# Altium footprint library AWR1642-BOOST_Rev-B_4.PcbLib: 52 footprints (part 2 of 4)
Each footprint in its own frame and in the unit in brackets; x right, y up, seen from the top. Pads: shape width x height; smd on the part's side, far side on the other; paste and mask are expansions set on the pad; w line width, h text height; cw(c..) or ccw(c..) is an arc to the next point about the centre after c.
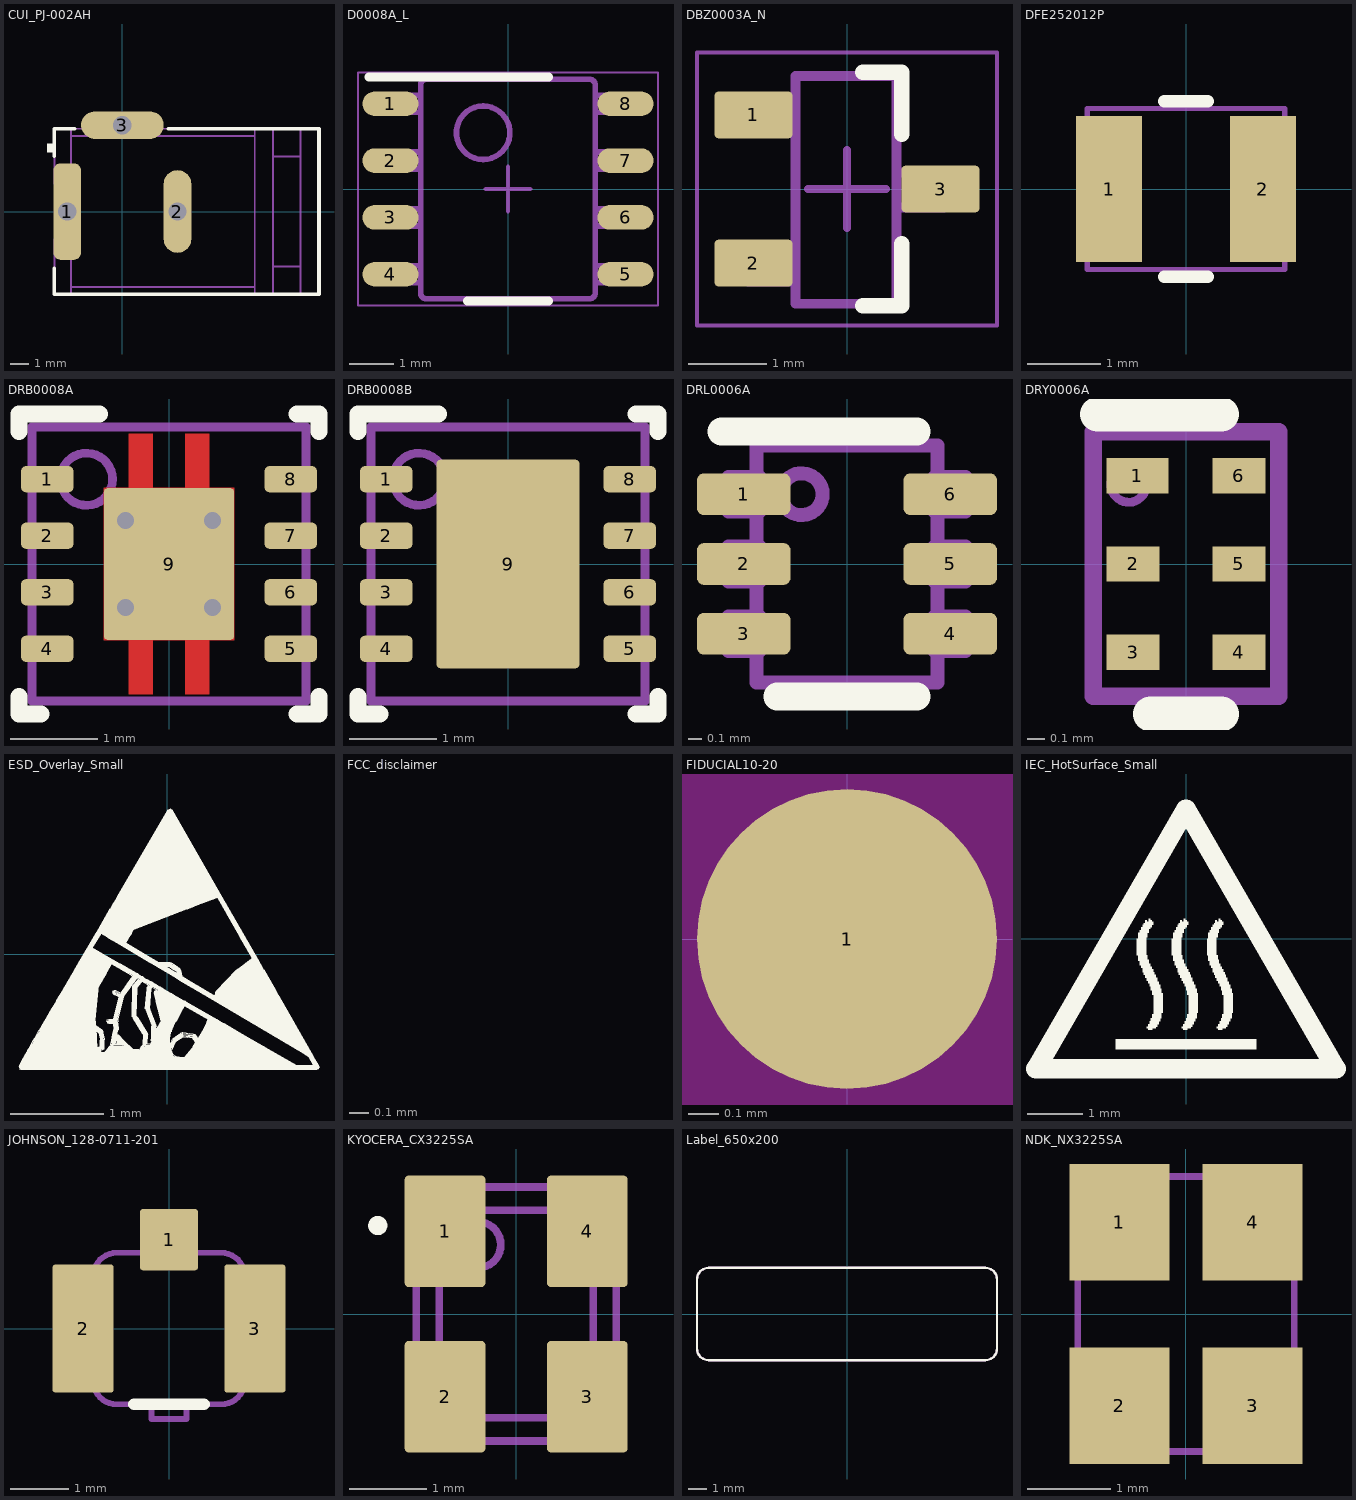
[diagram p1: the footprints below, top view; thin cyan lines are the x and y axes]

## CUI_PJ-002AH [mm] "DC POWER JACK, R/A, TH"
height 11.2
pads (3):
  rrect50% 1.5x5.25 hole 1 square: 1(-3,0)
  oval 1.5x4.5 hole 1 square: 2(3,0)
  oval 4.5x1.5 hole 1 square: 3(0,4.7)
Top Overlay:
  rectangle: -4.101,3.2 -3.701,3.7
  lines w0.2: -3.7,-3.1 -3.7,-4.5 -2.8,-4.5 7.2,-4.5 8.2,-4.5 9.7,-4.5 10.7,-4.5 10.7,4.5 9.7,4.5 8.2,4.5 7.2,4.5 2.5,4.5 ; -3.7,3 -3.7,4.5 -2.8,4.5 -2.6,4.5
Mechanical 5:
  lines w0.1: -1.25,4.5 -1.25,4.9 1.25,4.9 1.25,4.5 ; 7.2,-4.1 -2.8,-4.1 ; 7.2,4.1 -2.8,4.1 ; 8.2,-3 9.7,-3 ; 8.2,3 9.7,3 ; -3.18,-1.5 -3.18,1.5 ; -3.18,-1.5 -3.7,-1.5 -3.7,-4.5 -2.8,-4.5 ; -3.18,-1.5 -2.82,-1.5 -2.82,1.5 -3.18,1.5 ; -3.18,1.5 -3.7,1.5 -3.7,4.5 -2.8,4.5 ; -2.8,-4.5 -2.8,-4.1 ; -2.8,-4.5 7.2,-4.5 ; -2.8,-4.1 -2.8,4.1 ; -2.8,4.1 -2.8,4.5 ; -2.8,4.5 7.2,4.5 ; 7.2,-4.5 7.2,4.5 ; 7.2,-4.5 8.2,-4.5 ; 7.2,4.5 8.2,4.5 ; 8.2,-4.5 8.2,4.5 ; 8.2,-4.5 9.7,-4.5 ; 8.2,4.5 9.7,4.5 ; 9.7,-4.5 9.7,4.5 ; 9.7,-4.5 10.7,-4.5 10.7,4.5 9.7,4.5
  text ".Designator" at -4.632,-0.63 h1.02
3D body: height 11, standoff -3.5, extent -3.7,-4.5 10.7,4.9

## D0008A_L [mm] "SOIC, 8-Leads, Body 4.9x3.9mm, Pitch 1.27mm, IPC High Density"
height 1.75
pads (8):
  oval 1.25x0.55 smd: 1(-2.625,1.905) 2(-2.625,0.635) 3(-2.625,-0.635) 4(-2.625,-1.905) 5(2.625,-1.905) 6(2.625,-0.635) 7(2.625,0.635) 8(2.625,1.905)
Top Overlay:
  lines w0.2: -3.1,2.5 0.9,2.5 ; -0.9,-2.5 0.9,-2.5
Mechanical 5:
  lines w0.127: -2.375,-2.095 -1.995,-2.095 -1.952,-2.095 -1.952,-1.715 -1.995,-1.715 -2.375,-1.715 ; -2.375,-2.095 -2.589,-2.095 -3.002,-2.095 -3.002,-1.715 -2.589,-1.715 -2.375,-1.715 ; -2.375,-2.095 -2.375,-1.715 ; -2.375,-0.825 -1.995,-0.825 -1.952,-0.825 -1.952,-0.445 -1.995,-0.445 -2.375,-0.445 ; -2.375,-0.825 -2.589,-0.825 -3.002,-0.825 -3.002,-0.445 -2.589,-0.445 -2.375,-0.445 ; -2.375,-0.825 -2.375,-0.445 ; -2.375,0.445 -1.995,0.445 -1.952,0.445 -1.952,0.825 -1.995,0.825 -2.375,0.825 ; -2.375,0.445 -2.589,0.445 -3.002,0.445 -3.002,0.825 -2.589,0.825 -2.375,0.825 ; -2.375,0.445 -2.375,0.825 ; -2.375,1.715 -1.995,1.715 -1.952,1.715 -1.952,2.095 -1.995,2.095 -2.375,2.095 ; -2.375,1.715 -2.589,1.715 -3.002,1.715 -3.002,2.095 -2.589,2.095 -2.375,2.095 ; -2.375,1.715 -2.375,2.095 ; -0.332,-2.45 -1.825,-2.45 -1.826,-2.45 cw(c-1.825,-2.323) -1.952,-2.324 -1.952,-2.323 -1.952,2.323 -1.952,2.324 cw(c-1.825,2.323) -1.826,2.45 -1.825,2.45 -0.332,2.45 ; -0.332,-2.45 -0.182,-2.45 ; -0.332,-2.45 -0.182,-2.45 ; -0.332,2.45 -0.182,2.45 ; -0.332,2.45 -0.182,2.45 ; -0.182,-2.45 0.178,-2.45 ; -0.182,2.45 0.178,2.45 ; 0.178,-2.45 0.328,-2.45 ; 0.178,-2.45 0.328,-2.45 ; 0.178,2.45 0.328,2.45 ; 0.178,2.45 0.328,2.45 ; 0.328,-2.45 1.821,-2.45 1.822,-2.45 ccw(c1.821,-2.323) 1.948,-2.324 1.948,-2.323 1.948,2.323 1.948,2.324 ccw(c1.821,2.323) 1.822,2.45 1.821,2.45 0.328,2.45 ; 2.371,-2.095 2.585,-2.095 2.998,-2.095 2.998,-1.715 2.585,-1.715 2.371,-1.715 ; 2.371,-2.095 1.991,-2.095 1.948,-2.095 1.948,-1.715 1.991,-1.715 2.371,-1.715 ; 2.371,-2.095 2.371,-1.715 ; 2.371,-0.825 2.585,-0.825 2.998,-0.825 2.998,-0.445 2.585,-0.445 2.371,-0.445 ; 2.371,-0.825 1.991,-0.825 1.948,-0.825 1.948,-0.445 1.991,-0.445 2.371,-0.445 ; 2.371,-0.825 2.371,-0.445 ; 2.371,0.445 2.585,0.445 2.998,0.445 2.998,0.825 2.585,0.825 2.371,0.825 ; 2.371,0.445 1.991,0.445 1.948,0.445 1.948,0.825 1.991,0.825 2.371,0.825 ; 2.371,0.445 2.371,0.825 ; 2.371,1.715 2.585,1.715 2.998,1.715 2.998,2.095 2.585,2.095 2.371,2.095 ; 2.371,1.715 1.991,1.715 1.948,1.715 1.948,2.095 1.991,2.095 2.371,2.095 ; 2.371,1.715 2.371,2.095 ; -0.555,0.659 cw(c-0.555,1.256) -0.555,1.853 cw(c-0.555,1.256) -0.555,0.659
  text ".Designator" at 0.61,-1.071 h0.89
Mechanical 15:
  lines w0.05: -3.35,-2.6 -3.35,2.6 3.35,2.6 3.35,-2.6 -3.35,-2.6
  lines w0.1: -0.5,0 0.5,0 ; 0,-0.5 0,0.5
3D body: height 1.63, standoff 0, extent -3,-2.45 3,2.45

## DBZ0003A_N [mm] "SOT23, 3-Leads, Body 2.9x1.3mm, Pitch 0.95mm, Lead Span 2.4mm, IPC Medium Density"
height 1.12
pads (3):
  rrect17% 1x0.6 smd: 1(-1.2,0.95) 2(-1.2,-0.95) 3(1.2,0)
Top Overlay:
  lines w0.2: 0.2,-1.5 0.7,-1.5 0.7,-0.7 ; 0.2,1.5 0.7,1.5 0.7,0.7
Mechanical 5:
  lines w0.127: -1.27,-1.187 -1.27,-0.743 -1.063,-0.743 -1.005,-0.743 -0.814,-0.743 -0.66,-0.743 -0.66,-1.187 -0.814,-1.187 -1.005,-1.187 -1.063,-1.187 -1.27,-1.187 ; -1.27,0.718 -1.27,1.162 -1.063,1.162 -1.005,1.162 -0.814,1.162 -0.66,1.162 -0.66,0.718 -0.814,0.718 -1.005,0.718 -1.063,0.718 -1.27,0.718 ; -0.66,-1.473 -0.66,1.448 0.635,1.448 0.635,-1.473 -0.66,-1.473 ; 0.635,-0.235 0.789,-0.235 0.98,-0.235 1.037,-0.235 1.245,-0.235 1.245,0.21 1.037,0.21 0.98,0.21 0.789,0.21 0.635,0.21 0.635,-0.235
  text ".Designator" at 0.226,-0.391 h0.51
Mechanical 15:
  lines w0.05: -1.925,-1.75 1.925,-1.75 1.925,1.75 -1.925,1.75 -1.925,-1.75
  lines w0.1: -0.5,0 0.5,0 ; 0,-0.5 0,0.5
3D body: height 0.98, standoff 0, extent -1.257,-1.461 1.258,1.461

## DFE252012P [mm] "TOKO, Pad sizes increased as per request"
height 1.2
pads (2):
  rect 0.9x2 smd: 1(-1.05,0) 2(1.05,0)
Top Overlay:
  lines w0.17: -0.3,-1.2 0.3,-1.2 ; -0.3,1.2 0.3,1.2
Mechanical 5:
  lines w0.07: -1.35,-1.1 1.35,-1.1 1.35,1.1 -1.35,1.1 -1.35,-1.1
  text ".Designator" at -0.949,-0.301 h0.7
3D body: height 1.2, standoff 0, extent -0.599,-1.099 0.599,1.099
3D body: height 1.2, standoff 0, extent 0.601,-1.099 1.349,1.099
3D body: height 1.2, standoff 0, extent -1.349,-1.099 -0.601,1.099

## DRB0008A [mm] "SON, 8-Leads, Body 3x3mm, Pitch 0.65mm, Thermal Pad 1.75x1.5mm, TI Recommended"
height 1
pads (9):
  rrect33% 0.6x0.3 smd: 1(-1.4,0.975) 2(-1.4,0.325) 3(-1.4,-0.325) 4(-1.4,-0.975) 5(1.4,-0.975) 6(1.4,-0.325) 7(1.4,0.325) 8(1.4,0.975)
  rrect7% 1.5x1.75 smd paste-0.75: 9(0,0)
via 0.5,-0.5 diameter 0.5 hole 0.2
via -0.5,-0.5 diameter 0.5 hole 0.2
via -0.5,0.5 diameter 0.5 hole 0.2
via 0.5,0.5 diameter 0.5 hole 0.2
Top Layer:
  region: -0.465,-1.5 -0.465,-0.875 -0.75,-0.875 -0.75,0.875 -0.465,0.875 -0.465,1.5 -0.185,1.5 -0.185,0.875 0.185,0.875 0.185,1.5 0.465,1.5 0.465,0.875 0.75,0.875 0.75,-0.875 0.465,-0.875 0.465,-1.5 0.185,-1.5 0.185,-0.875 -0.185,-0.875 -0.185,-1.5
Top Overlay:
  lines w0.2: -1.725,-1.525 -1.725,-1.725 -1.475,-1.725 ; -1.725,1.525 -1.725,1.725 -0.8,1.725 ; 1.475,-1.725 1.725,-1.725 1.725,-1.525 ; 1.475,1.725 1.725,1.725 1.725,1.525
Top Paste:
  rectangle: -0.691,-0.793 0.691,0.793
Mechanical 5:
  circle w0.1: c-0.95,0.975 r0.3
  lines w0.1: -1.575,-1.575 1.575,-1.575 1.575,1.575 -1.575,1.575 -1.575,-1.575
  text ".Designator" at -0.194,-0.744 h0.76
3D body: height 1, standoff 0, extent -1.575,-1.575 1.575,1.575
3D body: height 1.01, standoff 0.8, extent -1.249,0.676 -0.651,1.274

## DRB0008B [mm] "SON, 8-Leads, Body 3x3mm, Pitch 0.65mm, Thermal Pad 2.4x1.65mm, TI Recommended"
height 1
pads (9):
  rrect33% 0.6x0.3 smd: 1(-1.4,0.975) 2(-1.4,0.325) 3(-1.4,-0.325) 4(-1.4,-0.975) 5(1.4,-0.975) 6(1.4,-0.325) 7(1.4,0.325) 8(1.4,0.975)
  rrect6% 1.65x2.4 smd paste-1.2: 9(0,0)
Top Overlay:
  lines w0.2: -1.725,-1.525 -1.725,-1.725 -1.475,-1.725 ; -1.725,1.525 -1.725,1.725 -0.8,1.725 ; 1.475,-1.725 1.725,-1.725 1.725,-1.525 ; 1.475,1.725 1.725,1.725 1.725,1.525
Top Paste:
  rectangle: -0.751,0.1 0.751,1.143
  rectangle: -0.751,-1.143 0.751,-0.1
Mechanical 5:
  circle w0.1: c-1.025,0.975 r0.3
  lines w0.1: -1.575,-1.575 1.575,-1.575 1.575,1.575 -1.575,1.575 -1.575,-1.575
  text ".Designator" at -0.719,-0.36 h0.76
3D body: height 0.96, standoff 0.01, extent -1.5,-1.5 1.5,1.5

## DRL0006A [mm] "SOTFL, 6-Flat Leads, Body 1.2x1.6x0.6mm, Pitch 0.5mm, TI recommended"
height 0.6
pads (6):
  rrect33% 0.67x0.3 smd: 1(-0.74,0.5) 2(-0.74,0) 3(-0.74,-0.5) 4(0.74,-0.5) 5(0.74,0) 6(0.74,0.5)
Top Overlay:
  lines w0.2: -0.9,0.95 0.5,0.95 ; -0.5,-0.95 0.5,-0.95
Mechanical 5:
  circle w0.1: c-0.325,0.5 r0.15
  lines w0.1: -0.65,-0.625 -0.65,-0.85 0.65,-0.85 0.65,-0.625 ; -0.65,-0.375 -0.65,-0.125 ; -0.65,0.125 -0.65,0.375 ; -0.65,0.625 -0.65,0.85 0.65,0.85 0.65,0.625 ; 0.65,-0.375 0.65,0.375 ; -0.85,-0.625 -0.627,-0.625 -0.627,-0.375 -0.85,-0.375 -0.85,-0.625 ; -0.85,-0.125 -0.85,0.125 -0.627,0.125 -0.627,-0.125 -0.85,-0.125 ; -0.85,0.375 -0.627,0.375 -0.627,0.625 -0.85,0.625 -0.85,0.375 ; 0.627,-0.625 0.85,-0.625 0.85,-0.375 0.627,-0.375 0.627,-0.625 ; 0.627,-0.125 0.627,0.125 0.85,0.125 0.85,-0.125 0.627,-0.125 ; 0.627,0.375 0.85,0.375 0.85,0.625 0.627,0.625 0.627,0.375
  text ".Designator" at 0.417,-0.514 h0.65
3D body: height 0.61, standoff 0.01, extent -0.8,-0.8 0.8,0.8

## DRY0006A [mm] "PSON, 6-Leads, Body 1x1.45mm, Pitch 0.5mm, TI Recommended"
height 0.6
pads (6):
  rect 0.35x0.2 smd: 1(-0.275,0.5)
  rect 0.3x0.2 smd: 2(-0.3,0) 3(-0.3,-0.5) 4(0.3,-0.5) 5(0.3,0) 6(0.3,0.5)
Top Overlay:
  lines w0.2: -0.5,0.85 0.2,0.85 ; -0.2,-0.85 0.2,-0.85
Mechanical 5:
  circle w0.05: c-0.325,0.45 r0.1
  lines w0.1: -0.525,-0.75 0.525,-0.75 0.525,0.75 -0.525,0.75 -0.525,-0.75
  text ".Designator" at 0.094,-0.514 h0.3
3D body: height 0.6, standoff 0, extent -0.525,-0.75 0.525,0.75
3D body: height 0.61, standoff 0.3, extent -0.424,0.351 -0.226,0.549

## ESD_Overlay_Small [mm]
Top Overlay:
  drawing of 901 lines, arcs and shapes, not listed

## FCC_disclaimer [mm]
height 0.6
Top Overlay:
  text "For evaluation only; /  not FCC approved for resale." at -14.654,1.93 h1.52

## FIDUCIAL10-20 [mm]
height 0.6
pads (1):
  round 1 smd mask+0.5: 1(0,0)
Top Layer keep-out:
  circle w1.178: c0,0 r0.5

## IEC_HotSurface_Small [mm]
Top Overlay:
  drawing of 10 lines, arcs and shapes, not listed

## JOHNSON_128-0711-201 [mm] "UMC Straight Jack Receptacle, 50 Ohm, SMT"
height 1.25
pads (3):
  rrect10% 1x1.05 smd: 1(0,1.525)
  rrect10% 1.05x2.2 smd: 2(-1.475,0) 3(1.475,0)
Top Overlay:
  lines w0.2: -0.6,-1.3 0.6,-1.3
Mechanical 5:
  lines w0.1: -0.3,1.3 -0.3,1.55 0.3,1.55 0.3,1.3 ; -1.3,-0.9 ccw(c-0.9,-0.9) -0.9,-1.3 -0.3,-1.3 -0.3,-1.55 0.3,-1.55 0.3,-1.3 0.9,-1.3 ccw(c0.9,-0.9) 1.3,-0.9 ; -1.3,-0.9 -1.5,-0.9 -1.5,0.9 -1.3,0.9 ; -1.3,-0.9 -1.3,0.9 ; -1.3,0.9 cw(c-0.9,0.9) -0.9,1.3 0.9,1.3 cw(c0.9,0.9) 1.3,0.9 ; 1.3,-0.9 1.5,-0.9 1.5,0.9 1.3,0.9 ; 1.3,-0.9 1.3,0.9
  text ".Designator" at -0.254,-0.265 h0.8
3D body: height 1.25, standoff 0, extent -1.5,-1.55 1.5,1.55

## KYOCERA_CX3225SA [mm] "SMD, 4-Leads, Body 3.2x2.5mm"
height 0.9
pads (4):
  rrect10% 1.05x1.45 smd: 1(-0.925,1.075) 2(-0.925,-1.075) 3(0.925,-1.075) 4(0.925,1.075)
Top Overlay:
  circle w0.125: c-1.8,1.15 r0.062
Mechanical 5:
  circle w0.1: c-0.5,0.9 r0.3
  lines w0.1: -1.3,-1.35 cw(c-1.3,-1.65) -1,-1.65 1,-1.65 cw(c1.3,-1.65) 1.3,-1.35 1.3,1.35 cw(c1.3,1.65) 1,1.65 -1,1.65 cw(c-1.3,1.65) -1.3,1.35 -1.3,-1.35 ; -1,-1.05 ccw(c-0.7,-1.05) -0.7,-1.35 0.7,-1.35 ccw(c0.7,-1.05) 1,-1.05 1,1.05 ccw(c0.7,1.05) 0.7,1.35 -0.7,1.35 ccw(c-0.7,1.05) -1,1.05 -1,-1.05
  text ".Designator" at -0.403,-0.275 h0.8
3D body: height 0.9, standoff 0.8, extent -0.799,0.601 -0.201,1.199
3D body: height 0.6, standoff 0, extent -1.301,-1.651 1.301,1.651
3D body: height 0.9, standoff 0.4, extent -0.999,-1.349 0.999,1.349

## Label_650x200 [mil] "Thermal Transfer Label"
height 1
pads (1):
  round 1 on Mech13: 0(0,0)
Top Overlay:
  lines w5: -325,-75 ccw(c-300,-75) -300,-100 300,-100 ccw(c300,-75) 325,-75 325,75 ccw(c300,75) 300,100 -300,100 ccw(c-300,75) -325,75 -325,-75
Mechanical 5:
  lines w5: -325,-75 ccw(c-300,-75) -300,-100 300,-100 ccw(c300,-75) 325,-75 325,75 ccw(c300,75) 300,100 -300,100 ccw(c-300,75) -325,75 -325,-75
  text ".Designator" at -60,-20 h40
3D body: height 1, standoff 0, extent -325.02,-100.02 325.02,100.02

## NDK_NX3225SA [mm] "NDK"
height 0.6
pads (4):
  rect 1.2x1.4 smd: 1(-0.8,1.1) 2(-0.8,-1.1) 3(0.8,-1.1) 4(0.8,1.1)
Mechanical 5:
  circle w0.08: c-0.8,1.1 r0.2
  lines w0.08: -1.3,-1.65 -1.3,1.65 1.3,1.65 1.3,-1.65 -1.3,-1.65
  text ".Designator" at 0.415,-0.739 h0.7
3D body: height 0.7, standoff 0, extent -1.3,-1.65 1.3,1.65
